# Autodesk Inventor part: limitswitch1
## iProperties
Shininess: 0.0
Created: 2002-01
Part Number: limitswitch1
Document SubType Name: Modeling
Density: 2.71 g/cm^3
Material: Aluminum-6061
Mass: 0.379544 g
Surface Area: 5.13202 cm^2
Volume: 0.140053 cm^3
Density: 0.0
Volumn: 0.0
Area: 0.0
PropertySet Name: Model Information
Control State: 0
Master: False
Checked Out: False
Author: Administrator
